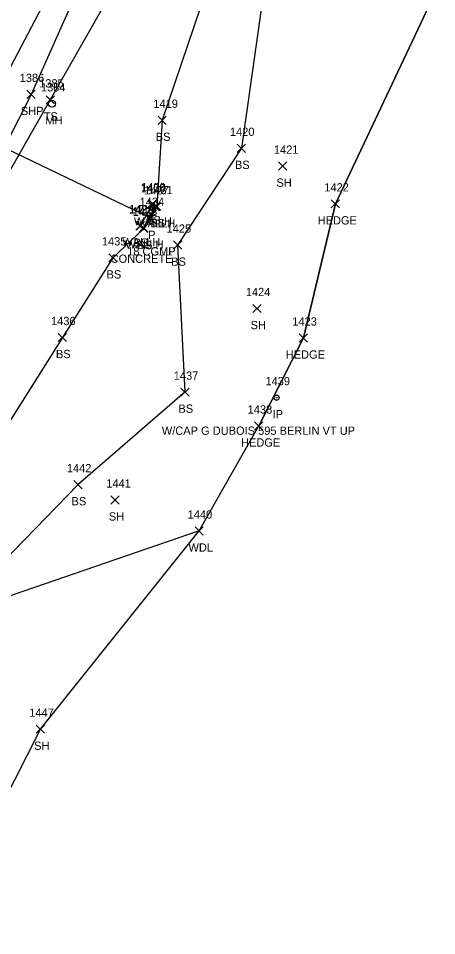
# Model space of a CAD drawing. Extents: x 1623612 to 1625808, y 621345 to 627748.
# Drawn here: x 1624593.5 to 1624694.8, y 625672.8 to 625894.9 of the extents above; entities that cross this region are included whole.
import ezdxf

# ---------------------------------------------------------------- set-up
doc = ezdxf.new("R2010")
doc.units = 0
for name, color, linetype in [('D_A', 7, 'Continuous'), ('D_C', 7, 'Continuous'), ('D_I', 7, 'Continuous'), ('D_TIC', 7, 'Continuous'), ('DCP', 7, 'Continuous'), ('DHW', 7, 'Continuous'), ('L_A', 7, 'Continuous'), ('L_I', 7, 'Continuous'), ('L_TIC', 7, 'Continuous'), ('LAHR', 7, 'Continuous'), ('LAWA', 7, 'Continuous'), ('LELB', 7, 'Continuous'), ('LSOGP', 7, 'Continuous'), ('M_A', 7, 'Continuous'), ('M_C', 7, 'Continuous'), ('M_I', 7, 'Continuous'), ('MPIR', 7, 'Continuous'), ('P_A', 7, 'Continuous'), ('P_I', 7, 'Continuous'), ('P_TIC', 7, 'Continuous'), ('PET', 7, 'Continuous'), ('PSP', 7, 'Continuous'), ('U_A', 7, 'Continuous'), ('U_I', 7, 'Continuous'), ('UUMH', 7, 'Continuous')]:
    doc.layers.add(name, color=color, linetype=linetype)

msp = doc.modelspace()

# ---------------------------------------------------------------- linework, layer by layer
at = {"layer": 'D_TIC'}
for points in [[(1624624.85, 625848.71), (1624626.85, 625850.71)], [(1624626.85, 625848.71), (1624624.85, 625850.71)], [(1624624.85, 625848.71), (1624626.85, 625850.71)], [(1624626.85, 625848.71), (1624624.85, 625850.71)], [(1624625.66, 625848.23), (1624627.66, 625850.23)], [(1624627.66, 625848.23), (1624625.66, 625850.23)], [(1624622.05, 625843.67), (1624624.05, 625845.67)], [(1624624.05, 625843.67), (1624622.05, 625845.67)], [(1624622.05, 625843.67), (1624624.05, 625845.67)], [(1624624.05, 625843.67), (1624622.05, 625845.67)], [(1624624.52, 625845.45), (1624626.52, 625847.45)], [(1624626.52, 625845.45), (1624624.52, 625847.45)], [(1624622.81, 625843.15), (1624624.81, 625845.15)], [(1624624.81, 625843.15), (1624622.81, 625845.15)]]:
    msp.add_lwpolyline(points, dxfattribs=at)
at = {"layer": 'DCP'}
msp.add_lwpolyline([(1624625.52, 625846.45), (1624544.09, 625885.52)], dxfattribs=at)
at = {"layer": 'DHW'}
for points in [[(1624625.85, 625849.71), (1624626.66, 625849.23), (1624623.81, 625844.15), (1624623.05, 625844.67)], [(1624625.85, 625849.71), (1624623.05, 625844.67)]]:
    msp.add_lwpolyline(points, dxfattribs=at)
at = {"layer": 'L_TIC'}
for points in [[(1624600.19, 625874.12), (1624602.19, 625876.12)], [(1624602.19, 625874.12), (1624600.19, 625876.12)], [(1624627.3, 625869.19), (1624629.3, 625871.19)], [(1624629.3, 625869.19), (1624627.3, 625871.19)], [(1624646.49, 625862.39), (1624648.49, 625864.39)], [(1624648.49, 625862.39), (1624646.49, 625864.39)], [(1624656.48, 625858.08), (1624658.48, 625860.08)], [(1624658.48, 625858.08), (1624656.48, 625860.08)], [(1624624.97, 625849), (1624626.97, 625851)], [(1624626.97, 625849), (1624624.97, 625851)], [(1624626.01, 625848.3), (1624628.01, 625850.3)], [(1624628.01, 625848.3), (1624626.01, 625850.3)], [(1624626.01, 625848.3), (1624628.01, 625850.3)], [(1624628.01, 625848.3), (1624626.01, 625850.3)], [(1624669.26, 625848.95), (1624671.26, 625850.95)], [(1624671.26, 625848.95), (1624669.26, 625850.95)], [(1624621.9, 625843.57), (1624623.9, 625845.57)], [(1624623.9, 625843.57), (1624621.9, 625845.57)], [(1624622.85, 625842.99), (1624624.85, 625844.99)], [(1624624.85, 625842.99), (1624622.85, 625844.99)], [(1624622.85, 625842.99), (1624624.85, 625844.99)], [(1624624.85, 625842.99), (1624622.85, 625844.99)], [(1624631.05, 625838.96), (1624633.05, 625840.96)], [(1624633.05, 625838.96), (1624631.05, 625840.96)], [(1624615.38, 625835.88), (1624617.38, 625837.88)], [(1624617.38, 625835.88), (1624615.38, 625837.88)], [(1624650.24, 625823.61), (1624652.24, 625825.61)], [(1624652.24, 625823.61), (1624650.24, 625825.61)], [(1624603.12, 625816.6), (1624605.12, 625818.6)], [(1624605.12, 625816.6), (1624603.12, 625818.6)], [(1624661.52, 625816.48), (1624663.52, 625818.48)], [(1624663.52, 625816.48), (1624661.52, 625818.48)], [(1624632.8, 625803.37), (1624634.8, 625805.37)], [(1624634.8, 625803.37), (1624632.8, 625805.37)], [(1624650.69, 625795.18), (1624652.69, 625797.18)], [(1624652.69, 625795.18), (1624650.69, 625797.18)], [(1624606.9, 625780.97), (1624608.9, 625782.97)], [(1624608.9, 625780.97), (1624606.9, 625782.97)], [(1624615.89, 625777.28), (1624617.89, 625779.28)], [(1624617.89, 625777.28), (1624615.89, 625779.28)], [(1624636.25, 625769.76), (1624638.25, 625771.76)], [(1624638.25, 625769.76), (1624636.25, 625771.76)], [(1624597.8, 625721.78), (1624599.8, 625723.78)], [(1624599.8, 625721.78), (1624597.8, 625723.78)]]:
    msp.add_lwpolyline(points, dxfattribs=at)
at = {"layer": 'LAHR'}
msp.add_lwpolyline([(1624775.42, 626076.07), (1624760.46, 626074.73), (1624753.03, 626056.16), (1624736.01, 626014.51), (1624724.67, 625982.95), (1624715.54, 625955.9), (1624695.74, 625903.84), (1624670.26, 625849.95), (1624662.52, 625817.48), (1624651.69, 625796.18)], dxfattribs=at)
at = {"layer": 'LAWA'}
msp.add_lwpolyline([(1624637.25, 625770.76), (1624576.85, 625750.09), (1624565.22, 625694.56), (1624521.74, 625653.69)], dxfattribs=at)
at = {"layer": 'LELB'}
for points in [[(1624955.96, 625983.78), (1624934.11, 626011.11), (1624911.27, 626037.79), (1624882.4, 626075.05), (1624844.35, 626119.9), (1624824.36, 626144.8), (1624806.17, 626164.83), (1624787.45, 626176.55), (1624783.93, 626178.73), (1624767.98, 626179.73), (1624754.07, 626176), (1624742, 626162.74), (1624739.77, 626159.16), (1624724.1, 626139.19), (1624712.05, 626114.81), (1624693.63, 626076.88), (1624682.43, 626045.31), (1624675.97, 626009.13), (1624661.01, 625972.63), (1624643.83, 625915.97), (1624628.3, 625870.19), (1624627.01, 625849.3)], [(1624955.96, 625983.78), (1624951.7, 625981.09), (1624926.74, 626006.44), (1624903, 626034.62), (1624876.22, 626070.88), (1624844.75, 626108.46), (1624819.16, 626140.11), (1624799.87, 626157.38), (1624783.22, 626162.54), (1624755.55, 626163.6), (1624745.94, 626159.17), (1624742.5, 626157.44), (1624728.24, 626136.03), (1624714.3, 626113.6), (1624699.16, 626074.97), (1624693.78, 626039.85), (1624688.78, 626004.07), (1624672.44, 625966.06), (1624654.5, 625913.12), (1624647.49, 625863.39), (1624632.05, 625839.96), (1624633.8, 625804.37), (1624607.9, 625781.97), (1624576.85, 625750.09)], [(1624703.97, 626118.88), (1624686.38, 626080.62), (1624681.08, 626059.17), (1624675.33, 626051.53), (1624659.81, 626015.24), (1624646.71, 625979.83), (1624626.49, 625919.66), (1624601.19, 625875.12), (1624577.24, 625833.33), (1624557.07, 625794.42), (1624540.93, 625764.23), (1624521.23, 625725.16), (1624501.1, 625688.94), (1624492.6, 625674.09)], [(1624625.97, 625850), (1624627.01, 625849.3), (1624623.85, 625843.99), (1624622.9, 625844.57)], [(1624623.85, 625843.99), (1624616.38, 625836.88), (1624604.12, 625817.6), (1624587.3, 625790.93), (1624564.35, 625753.47), (1624542.54, 625705.94), (1624515.98, 625657.65)]]:
    msp.add_lwpolyline(points, dxfattribs=at)
at = {"layer": 'LSOGP'}
msp.add_lwpolyline([(1624549.56, 625621.85), (1624579.98, 625685.81), (1624598.8, 625722.78), (1624637.25, 625770.76), (1624651.69, 625796.18), (1624662.52, 625817.48), (1624670.26, 625849.95), (1624695.74, 625903.84)], dxfattribs=at)
at = {"layer": 'MPIR'}
for radius in [0.625, 0.0833]:
    msp.add_circle((1624656.02, 625803.04), radius, dxfattribs=at)
at = {"layer": 'P_TIC'}
for points in [[(1624595.53, 625875.44), (1624597.53, 625877.44)], [(1624597.53, 625875.44), (1624595.53, 625877.44)]]:
    msp.add_lwpolyline(points, dxfattribs=at)
at = {"layer": 'PET'}
msp.add_lwpolyline([(1624697.29, 626122.48), (1624678.78, 626081.29), (1624660.95, 626038.77), (1624644.98, 625998.6), (1624626.67, 625954.13), (1624613.79, 625925.45), (1624589.8, 625879.72), (1624567.17, 625838.88), (1624546.44, 625801.43), (1624529.95, 625769.7), (1624509.63, 625731.24), (1624490.24, 625695.36), (1624481.98, 625680.63)], dxfattribs=at)
at = {"layer": 'PSP'}
msp.add_lwpolyline([(1624701.4, 626121.26), (1624681.91, 626079.85), (1624663.33, 626037.3), (1624647.64, 625997), (1624629.31, 625952.35), (1624617.52, 625923.63), (1624596.53, 625876.44), (1624575.28, 625834.53), (1624555.05, 625795.64), (1624539.05, 625764.96), (1624518.58, 625726.57), (1624499, 625690.51), (1624490.77, 625675.48)], dxfattribs=at)
at = {"layer": 'UUMH'}
for p, q in [((1624601.61, 625874.16), (1624601.61, 625874.16)), ((1624602.45, 625874.16), (1624602.45, 625874.16))]:
    msp.add_line(p, q, dxfattribs=at)
msp.add_circle((1624601.61, 625874.16), 0.833, dxfattribs=at)

# ---------------------------------------------------------------- texts
at = {"layer": 'D_A'}
for s, p in [('WALLH', (1624621.44, 625844.71)), ('WALLH', (1624621.44, 625844.71)), ('WALLH', (1624622.25, 625844.23)), ('P', (1624624.9, 625841.45)), ('WALLH', (1624618.64, 625839.67)), ('WALLH', (1624618.64, 625839.67)), ('WALLH', (1624619.4, 625839.15))]:
    msp.add_text(s, height=2, dxfattribs=at).set_placement(p)
at = {"layer": 'D_C'}
for s, p in [('18 CGMP', (1624619.81, 625837.45)), ('CONCRETE', (1624615.81, 625835.67)), ('CONCRETE', (1624615.81, 625835.67))]:
    msp.add_text(s, height=2, dxfattribs=at).set_placement(p)
at = {"layer": 'D_I'}
for s, p in [('1426', (1624623.1, 625852.71)), ('1426', (1624623.1, 625852.71)), ('1427', (1624623.96, 625852.23)), ('1429', (1624620.35, 625847.67)), ('1429', (1624620.35, 625847.67)), ('1434', (1624622.83, 625849.45)), ('1428', (1624621.12, 625847.15))]:
    msp.add_text(s, height=2, dxfattribs=at).set_placement(p)
at = {"layer": 'L_A'}
for s, p in [('TS', (1624599.6, 625870.12)), ('BS', (1624626.74, 625865.19)), ('BS', (1624645.93, 625858.39)), ('SH', (1624655.97, 625854.08)), ('BS', (1624624.41, 625845)), ('BS', (1624625.45, 625844.3)), ('BS', (1624625.45, 625844.3)), ('HEDGE', (1624665.96, 625844.95)), ('BS', (1624621.34, 625839.57)), ('BS', (1624622.29, 625838.99)), ('BS', (1624622.29, 625838.99)), ('BS', (1624630.49, 625834.96)), ('BS', (1624614.82, 625831.88)), ('SH', (1624649.73, 625819.61)), ('BS', (1624602.56, 625812.6)), ('HEDGE', (1624658.22, 625812.48)), ('BS', (1624632.24, 625799.37)), ('HEDGE', (1624647.39, 625791.18)), ('BS', (1624606.34, 625776.97)), ('SH', (1624615.37, 625773.28)), ('WDL', (1624634.67, 625765.76)), ('SH', (1624597.28, 625717.78))]:
    msp.add_text(s, height=2, dxfattribs=at).set_placement(p)
at = {"layer": 'L_I'}
for s, p in [('1385', (1624598.5, 625878.12)), ('1419', (1624626.16, 625873.19)), ('1420', (1624644.71, 625866.39)), ('1421', (1624655.35, 625862.08)), ('1430', (1624623.19, 625853)), ('1431', (1624624.89, 625852.3)), ('1431', (1624624.89, 625852.3)), ('1422', (1624667.57, 625852.95)), ('1433', (1624620.2, 625847.57)), ('1432', (1624621.16, 625846.99)), ('1432', (1624621.16, 625846.99)), ('1425', (1624629.36, 625842.96)), ('1435', (1624613.69, 625839.88)), ('1424', (1624648.55, 625827.61)), ('1436', (1624601.37, 625820.6)), ('1423', (1624659.83, 625820.48)), ('1437', (1624631.1, 625807.37)), ('1438', (1624649, 625799.18)), ('1442', (1624605.2, 625784.97)), ('1441', (1624614.76, 625781.28)), ('1440', (1624634.47, 625773.76)), ('1447', (1624596.1, 625725.78))]:
    msp.add_text(s, height=2, dxfattribs=at).set_placement(p)
at = {"layer": 'M_A'}
msp.add_text('IP', height=2, dxfattribs=at).set_placement((1624655.06, 625798.04))
at = {"layer": 'M_C'}
msp.add_text('W/CAP G DUBOIS 595 BERLIN VT UP', height=2, dxfattribs=at).set_placement((1624628.21, 625794.04))
at = {"layer": 'M_I'}
msp.add_text('1439', height=2, dxfattribs=at).set_placement((1624653.32, 625806.04))
at = {"layer": 'P_A'}
msp.add_text('SHP', height=2, dxfattribs=at).set_placement((1624594.06, 625871.44))
at = {"layer": 'P_I'}
msp.add_text('1386', height=2, dxfattribs=at).set_placement((1624593.78, 625879.44))
at = {"layer": 'U_A'}
msp.add_text('MH', height=2, dxfattribs=at).set_placement((1624599.98, 625869.16))
at = {"layer": 'U_I'}
msp.add_text('1384', height=2, dxfattribs=at).set_placement((1624598.92, 625877.16))

doc.saveas('drawing.dxf')
